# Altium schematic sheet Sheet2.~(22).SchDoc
size B; SheetNumber: 1; SheetTotal: 1
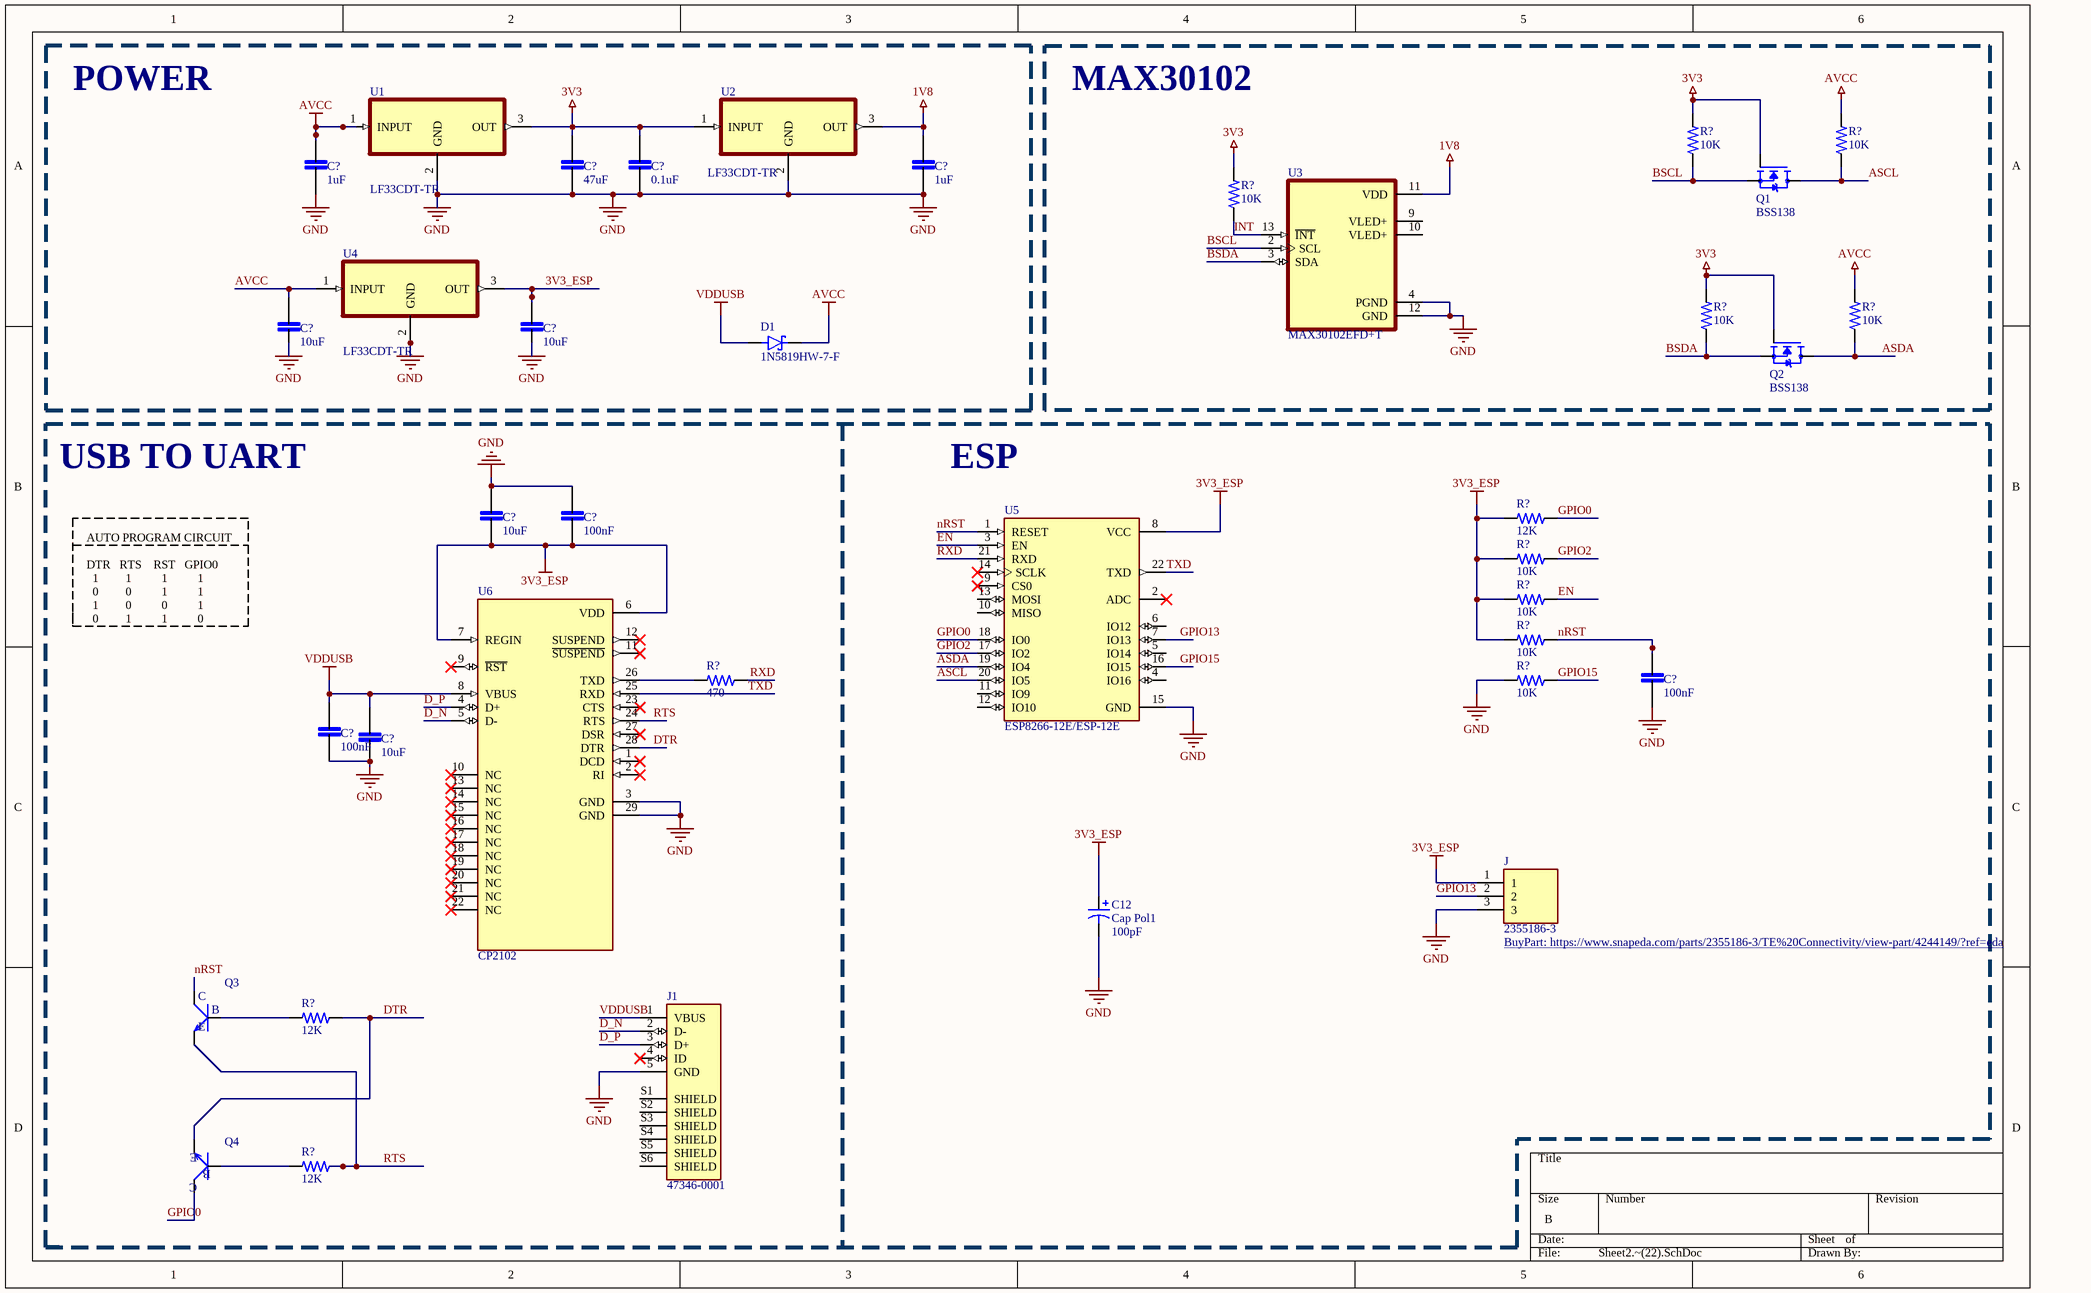
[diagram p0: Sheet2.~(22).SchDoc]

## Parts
(Parts that share a designator on the sheet are numbered #1, #2 ... from top to bottom, then left to right.)
C12  Cap Pol1  value 100pF  [RB7.6-15]
C?#1  1uF  [CAPC2012X140N]
C?#2  47uF  [CAPC2012X140N]
C?#3  0.1uF  [CAPC2012X140N]
C?#4  1uF  [CAPC2012X140N]
C?#5  10uF  [CAPC2012X140N]
C?#6  10uF  [CAPC2012X140N]
C?#7  10uF  [CAPC2012X140N]
C?#8  100nF  [CAPC2012X140N]
C?#9  100nF  [CAPC2012X140N]
C?#10  100nF  [CAPC2012X140N]
C?#11  10uF  [CAPC2012X140N]
D1  1N5819HW-7-F  [SOD3715X145N]
J  2355186-3  [TE_2355186-3]
J1  47346-0001  [MOLEX_47346-0001]
Q1  BSS138  [SOT95P240X111-3N]
Q2  BSS138  [SOT95P240X111-3N]
Q3  SMD-TRANSISTORS-NPN-25V-500MW(SOT-23)  [SOT-23]  (value not drawn)
Q4  SMD-TRANSISTORS-NPN-25V-500MW(SOT-23)  [SOT-23]  (value not drawn)
R?#1  10K  [RESC2012X65N]
R?#2  10K  [RESC2012X65N]
R?#3  10K  [RESC2012X65N]
R?#4  10K  [RESC2012X65N]
R?#5  10K  [RESC2012X65N]
R?#6  12K  [RESC2012X65N]
R?#7  10K  [RESC2012X65N]
R?#8  10K  [RESC2012X65N]
R?#9  10K  [RESC2012X65N]
R?#10  470  [RESC2012X65N]
R?#11  10K  [RESC2012X65N]
R?#12  12K  [RESC2012X65N]
R?#13  12K  [RESC2012X65N]
U1  LF33CDT-TR  [TO228P972X240-3N]
U2  LF33CDT-TR  [TO228P972X240-3N]
U3  MAX30102EFD+T  [XDCR_MAX30101EFD+]
U4  LF33CDT-TR  [TO228P972X240-3N]
U5  ESP8266-12E/ESP-12E  [XCVR_ESP8266-12E/ESP-12E]
U6  CP2102  [QFN50P500X500X100-29N]

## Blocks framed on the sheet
POWER: C?#1-C?#6 D1 U1 U2 U4

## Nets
1V8: C?#4.2 U2.3(OUT) U3.11(VDD)
3V3: C?#2.2 C?#3.2 Q1.1(G) Q2.1(G) R?#1.2 R?#3.2 R?#4.2 U1.3(OUT) U2.1(INPUT)
3V3_ESP: C12.1 C?#6.2 C?#7.1 C?#8.1 J.1 R?#6.2 R?#7.2 R?#8.2 R?#9.2 U4.3(OUT) U5.8(VCC) U6.6(VDD) U6.7(REGIN)
AVCC: C?#1.2 C?#5.2 D1.C(K) R?#2.2 R?#5.2 U1.1(INPUT) U4.1(INPUT)
GND: C12.2 C?#1.1 C?#2.1 C?#3.1 C?#4.1 C?#5.1 C?#6.1 C?#7.2 C?#8.2 C?#9.1 C?#10.1 C?#11.1 J.3 J1.5(GND) R?#11.2 U1.2(GND) U2.2(GND) U3.4(PGND) U3.12(GND) U4.2(GND) U5.15(GND) U6.3(GND) U6.29(GND)
VDDUSB: C?#10.2 C?#11.2 D1.A J1.1(VBUS) U6.8(VBUS)
ASCL: Q1.3(D) R?#2.1 U5.20(IO5)
ASDA: Q2.3(D) R?#5.1 U5.19(IO4)
BSCL: Q1.2(S) R?#1.1 U3.2(SCL)
BSDA: Q2.2(S) R?#4.1 U3.3(SDA)
D_N: J1.2(D-) U6.5(D-)
D_P: J1.3(D+) U6.4(D+)
DTR: Q4.2(E) R?#12.1 U6.28(DTR)
EN: R?#8.1 U5.3(EN)
GPIO0: Q4.3(C) R?#6.1 U5.18(IO0)
GPIO2: R?#7.1 U5.17(IO2)
GPIO13: J.2 U5.7(IO13)
GPIO15: R?#11.1 U5.16(IO15)
INT: R?#3.1 U3.13(~{INT})
nRST: C?#9.2 Q3.3(C) R?#9.1 U5.1(RESET)
RTS: Q3.2(E) R?#13.1 U6.24(RTS)
RXD: R?#10.1 U5.21(RXD)
TXD: U5.22(TXD) U6.25(RXD)
NetQ3_1: Q3.1(B) R?#12.2
NetQ4_1: Q4.1(B) R?#13.2
NetR?#10_2: R?#10.2 U6.26(TXD)

Not connected (* = marked no-connect by the designer): J1 4(ID)* S1(SHIELD) S2(SHIELD) S3(SHIELD) S4(SHIELD) S5(SHIELD) S6(SHIELD); U3 9(VLED+) 10(VLED+); U5 2(ADC)* 4(IO16) 5(IO14) 6(IO12) 9(CS0)* 10(MISO) 11(IO9) 12(IO10) 13(MOSI) 14(SCLK)*; U6 1(DCD)* 2(RI)* 9(~{RST})* 10(NC)* 11(~{SUSPEND})* 12(SUSPEND)* 13(NC)* 14(NC)* 15(NC)* 16(NC)* 17(NC)* 18(NC)* 19(NC)* 20(NC)* 21(NC)* 22(NC)* 23(CTS)* 27(DSR)*

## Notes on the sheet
- MAX30102
- USB TO UART
- ESP
- AUTO PROGRAM CIRCUIT
  DTR   RTS    RST   GPIO0
  1         1          1          1
  0         0          1          1
  1         0          0          1
  0         1          1          0

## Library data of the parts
C12 = Cap Pol1: Polarized Capacitor (Radial)
C?#1-C?#11 = LD051C121KAB2A: Ceramic Capacitor; MF: AVX
D1 = 1N5819HW-7-F: Diode Schottky 40 V 1A Surface Mount SOD-123; MF: Diodes Inc.
J = 2355186-3: Pin 3P,2MM,BRK HDR,SRVT,2.8,0.76AU,BOX 3 POS; MF: TE Connectivity
J1 = 47346-0001: USB - micro B USB 2.0 Receptacle Connector 5 Position Surface Mount, Right Angle; MF: Molex
Q1 Q2 = BSS138: N-Channel 50 V 220mA (Ta) 350mW (Ta) Surface Mount SOT-23-3; MF: onsemi
Q3 Q4 = SMD-TRANSISTORS-NPN-25V-500MW(SOT-23): Bipolar (BJT) Transistor NPN 25 V 500 mA 150MHz 300 mW Surface Mount SOT-23; MF: UMW; MP: S8050
R?#1-R?#13 = 2-2176053-0: RES 0.33 OHM 1% 1/4W 0805; Power_Rating: .25 W; Resistance: .33; MF: TE Connectivity
U1 U2 U4 = LF33CDT-TR: Linear Voltage Regulator IC Positive Fixed 1 Output 500mA DPAK; MF: STMicroelectronics
U3 = MAX30102EFD+T: Pulse Oximeter and Heart Rate Sensor Digital Output; MF: Maxim Integrated Products
U5 = ESP8266-12E/ESP-12E: This WiFi module has a 32-bit MCU micro and clock speeds supporting 80 MHz or 160 MHz. Supports the RTOS and integrated Wi-Fi MAC/BB/RF/PA/LNA, and has an on-board antenna.; MF: AI-Thinker
U6 = CP2102: CP2102N USB 2.0 to UART (RS232) Bridge Interface Evaluation Board; MF: Silicon Labs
